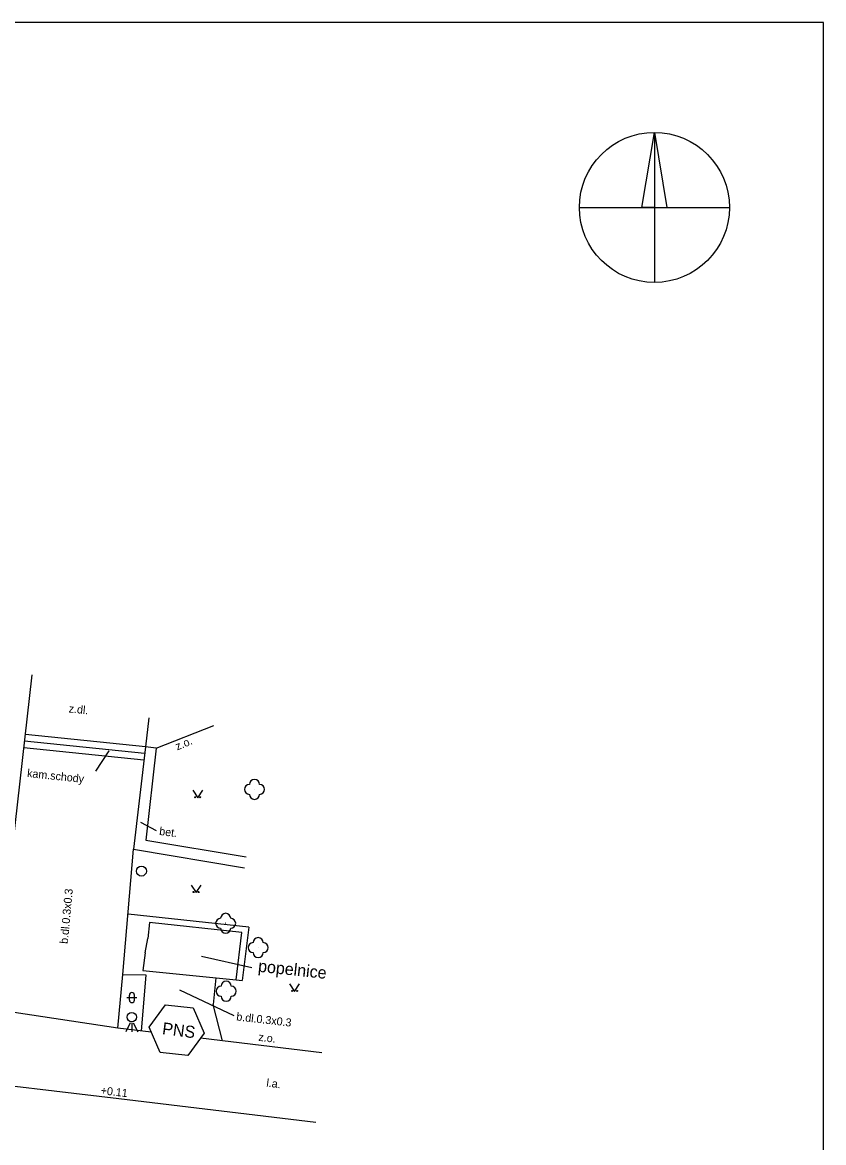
# Model space of a CAD drawing. Extents: x -597333 to -596488, y -1158921 to -1158644.
# Drawn here: x -596528.2 to -596488.1, y -1158706.7 to -1158650.7 of the extents above; entities that cross this region are included whole.
import ezdxf

# ---------------------------------------------------------------- set-up
doc = ezdxf.new("R2010")
doc.units = 0
for name, color, linetype in [('Vrstva 1', 7, 'Continuous'), ('Vrstva 12', 7, 'Continuous'), ('Vrstva 14', 7, 'Continuous'), ('Vrstva 15', 7, 'Continuous'), ('Vrstva 17', 7, 'Continuous'), ('Vrstva 25', 7, 'Continuous'), ('Vrstva 4', 7, 'Continuous'), ('Vrstva 44', 7, 'Continuous'), ('Vrstva 49', 7, 'Continuous'), ('Vrstva 5', 7, 'Continuous'), ('Vrstva 50', 7, 'Continuous'), ('Vrstva 52', 7, 'Continuous'), ('Vrstva 7', 7, 'Continuous')]:
    doc.layers.add(name, color=color, linetype=linetype)

msp = doc.modelspace()

# ---------------------------------------------------------------- linework, layer by layer
at = {"layer": 'Vrstva 1'}
msp.add_lwpolyline([(-596698.148, -1158650.657), (-596698.148, -1158799.157), (-596488.148, -1158799.157), (-596488.148, -1158650.657)], close=True, dxfattribs=at)
at = {"layer": 'Vrstva 12'}
msp.add_lwpolyline([(-596522.067, -1158697.172), (-596522.172, -1158698.052), (-596517.51, -1158698.52), (-596517.223, -1158696.147), (-596521.849, -1158695.653), (-596521.937, -1158696.45)], dxfattribs=at)
at = {"layer": 'Vrstva 14'}
for p, q in [((-596522.847, -1158699.531), (-596522.847, -1158699.281)), ((-596522.597, -1158699.531), (-596522.597, -1158699.281)), ((-596522.972, -1158699.406), (-596522.472, -1158699.406))]:
    msp.add_line(p, q, dxfattribs=at)
for points in [[(-596519.686, -1158689.045), (-596519.436, -1158689.42), (-596519.186, -1158689.045)], [(-596519.769, -1158693.78), (-596519.519, -1158694.155), (-596519.269, -1158693.78)], [(-596514.843, -1158698.727), (-596514.593, -1158699.102), (-596514.343, -1158698.727)]]:
    msp.add_lwpolyline(points, dxfattribs=at)
for centre, radius in [((-596516.598, -1158688.998), 0.00025), ((-596519.561, -1158689.395), 0.025), ((-596519.311, -1158689.395), 0.025), ((-596519.644, -1158694.13), 0.025), ((-596519.394, -1158694.13), 0.025), ((-596518.038, -1158695.695), 0.00025), ((-596516.413, -1158696.91), 0.00025), ((-596518.013, -1158699.091), 0.00025), ((-596514.718, -1158699.077), 0.025), ((-596514.468, -1158699.077), 0.025)]:
    msp.add_circle(centre, radius, dxfattribs=at)
for centre, radius, start, end in [((-596516.598, -1158688.748), 0.25, 0, 180), ((-596516.848, -1158688.998), 0.25, 90, 270), ((-596516.598, -1158689.248), 0.25, 180, 360), ((-596516.348, -1158688.998), 0.25, 270, 90), ((-596518.288, -1158695.695), 0.25, 90, 270), ((-596518.038, -1158695.445), 0.25, 0, 180), ((-596517.788, -1158695.695), 0.25, 270, 90), ((-596518.038, -1158695.945), 0.25, 180, 360), ((-596516.413, -1158696.66), 0.25, 0, 180), ((-596516.663, -1158696.91), 0.25, 90, 270), ((-596516.163, -1158696.91), 0.25, 270, 90), ((-596516.413, -1158697.16), 0.25, 180, 360), ((-596518.013, -1158698.841), 0.25, 0, 180), ((-596522.722, -1158699.281), 0.125, 0, 180), ((-596518.263, -1158699.091), 0.25, 90, 270), ((-596518.013, -1158699.341), 0.25, 180, 360), ((-596517.763, -1158699.091), 0.25, 270, 90), ((-596522.722, -1158699.531), 0.125, 180, 360)]:
    msp.add_arc(centre, radius, start, end, dxfattribs=at)
at = {"layer": 'Vrstva 15'}
for points in [[(-596522.053, -1158686.871), (-596528.051, -1158686.257)], [(-596522.129, -1158687.533), (-596528.125, -1158686.919)], [(-596522.091, -1158687.202), (-596528.088, -1158686.588)]]:
    msp.add_lwpolyline(points, dxfattribs=at)
at = {"layer": 'Vrstva 17'}
for points in [[(-596542.176, -1158689.473), (-596542.736, -1158694.52), (-596529.158, -1158696.128), (-596527.716, -1158683.272)], [(-596522.053, -1158686.871), (-596522.642, -1158691.989), (-596517.097, -1158692.916)], [(-596521.507, -1158686.934), (-596522.053, -1158686.871)], [(-596521.507, -1158686.934), (-596522.036, -1158691.533), (-596517.006, -1158692.374)]]:
    msp.add_lwpolyline(points, dxfattribs=at)
at = {"layer": 'Vrstva 25'}
msp.add_circle((-596522.249, -1158693.085), 0.25, dxfattribs=at)
at = {"layer": 'Vrstva 4'}
for p, q in [((-596521.87, -1158700.89), (-596521.05, -1158699.77)), ((-596521.05, -1158699.77), (-596519.67, -1158699.92)), ((-596519.67, -1158699.92), (-596519.11, -1158701.19)), ((-596521.31, -1158702.16), (-596521.87, -1158700.89)), ((-596519.11, -1158701.19), (-596519.93, -1158702.31)), ((-596519.93, -1158702.31), (-596521.31, -1158702.16))]:
    msp.add_line(p, q, dxfattribs=at)
at = {"layer": 'Vrstva 44'}
for p, q in [((-596522.804, -1158700.673), (-596523.03, -1158701.125)), ((-596522.73, -1158700.675), (-596522.73, -1158701.125)), ((-596522.655, -1158700.673), (-596522.43, -1158701.125))]:
    msp.add_line(p, q, dxfattribs=at)
msp.add_circle((-596522.73, -1158700.38), 0.234, dxfattribs=at)
at = {"layer": 'Vrstva 49'}
for p, q in [((-596523.873, -1158687.072), (-596524.543, -1158688.094)), ((-596522.295, -1158690.644), (-596521.514, -1158691.048)), ((-596516.727, -1158697.915), (-596519.243, -1158697.348)), ((-596517.608, -1158700.316), (-596520.329, -1158699.032))]:
    msp.add_line(p, q, dxfattribs=at)
at = {"layer": 'Vrstva 5'}
msp.add_lwpolyline([(-596522.067, -1158697.172), (-596521.937, -1158696.45)], dxfattribs=at)
at = {"layer": 'Vrstva 52'}
for p, q in [((-596496.605, -1158656.158), (-596495.98, -1158659.908)), ((-596500.355, -1158659.908), (-596492.855, -1158659.908)), ((-596496.605, -1158659.908), (-596496.605, -1158663.658))]:
    msp.add_line(p, q, dxfattribs=at)
msp.add_lwpolyline([(-596496.605, -1158656.158), (-596496.605, -1158659.908), (-596497.23, -1158659.908)], close=True, dxfattribs=at)
msp.add_circle((-596496.605, -1158659.908), 3.75, dxfattribs=at)
at = {"layer": 'Vrstva 7'}
for p, q in [((-596521.886, -1158685.426), (-596522.053, -1158686.871)), ((-596523.43, -1158700.94), (-596523.175, -1158698.254)), ((-596518.53, -1158698.418), (-596518.664, -1158699.748))]:
    msp.add_line(p, q, dxfattribs=at)
for points in [[(-596521.507, -1158686.934), (-596518.63, -1158685.801)], [(-596523.175, -1158698.254), (-596522.642, -1158691.989)], [(-596516.888, -1158695.882), (-596522.918, -1158695.236)], [(-596516.888, -1158695.882), (-596517.213, -1158698.556)], [(-596523.175, -1158698.254), (-596522.027, -1158698.269), (-596522.258, -1158701.08)], [(-596517.51, -1158698.52), (-596517.213, -1158698.556)], [(-596518.191, -1158701.568), (-596518.664, -1158699.748)], [(-596521.76, -1158701.14), (-596523.43, -1158700.94), (-596529.511, -1158700.028)], [(-596513.223, -1158702.162), (-596519.29, -1158701.436)], [(-596532.113, -1158703.424), (-596523.38, -1158704.46), (-596513.538, -1158705.641)]]:
    msp.add_lwpolyline(points, dxfattribs=at)

# ---------------------------------------------------------------- texts
at = {"layer": 'Vrstva 49'}
for s, height, rotation, p in [('z.dl.', 0.4, 354.4012, (-596525.899, -1158685.151)), ('z.o.', 0.4, 22.4301, (-596520.456, -1158687.054)), ('kam.schody', 0.4, 353.9728, (-596527.978, -1158688.376)), ('bet.', 0.4, 352.7832, (-596521.376, -1158691.277)), ('b.dl.0.3x0.3', 0.4, 84.6488, (-596525.933, -1158696.735)), ('popelnice', 0.6, 353.9633, (-596516.439, -1158698.114)), ('b.dl.0.3x0.3', 0.4, 353.407, (-596517.519, -1158700.547)), ('PNS', 0.6, 352.6773, (-596521.235, -1158701.234)), ('z.o.', 0.4, 353.0646, (-596516.416, -1158701.565)), ('l.a.', 0.4, 352.2447, (-596516.019, -1158703.849))]:
    msp.add_text(s, height=height, rotation=rotation, dxfattribs=at).set_placement(p)
at = {"layer": 'Vrstva 50'}
msp.add_text('+0.11', height=0.4, rotation=353.6116, dxfattribs=at).set_placement((-596524.301, -1158704.237))

doc.saveas('drawing.dxf')
